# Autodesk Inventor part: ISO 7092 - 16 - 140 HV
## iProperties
Comments: To add or edit properties for Autodesk Inventor files, use iProperties.
Created: 2004-01
Part Number: ISO 7092 - 16 - 140 HV
Vendor: Autodesk Inc.
Document SubType Name: Modeling
Designer: Administratör
Material: Standard
Description: Bricka
Standard: ISO 7092
Alert: To add or edit properties for Autodesk Inventor files, use iProperties.
Control State: 0
Master: False
Checked Out: False
Shininess: 64.0
Length Units: 11269
Angle Units: 11279
Time Units: 11290
Mass Units: 11283
Length Display Precision: 3
Angle Display Precision: 2
Compacted: True
Density: 0.0
Volumn: 0.0
Area: 0.0
PropertySet Name: Model Information
Author: Administratör
Revision Number: 8
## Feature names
1. Kropp [Extrusion]
